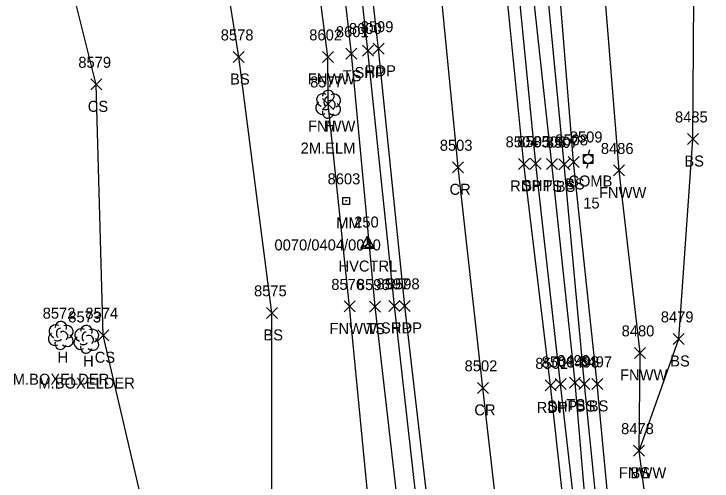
# Model space of a CAD drawing. Extents: x 1439173 to 1457902, y 641926 to 659889.
# Drawn here: x 1448293 to 1448419.9, y 645547.6 to 645632.4 of the extents above; entities that cross this region are included whole.
import ezdxf

# ---------------------------------------------------------------- set-up
doc = ezdxf.new("R2010")
doc.units = 0
for name, color, linetype in [('C_A', 7, 'Continuous'), ('C_I', 7, 'Continuous'), ('CPSM', 7, 'Continuous'), ('L_A', 7, 'Continuous'), ('L_C', 7, 'Continuous'), ('L_I', 7, 'Continuous'), ('L_TIC', 7, 'Continuous'), ('LELB', 7, 'Continuous'), ('LFNC', 7, 'Continuous'), ('LTD', 7, 'Continuous'), ('P_A', 7, 'Continuous'), ('P_I', 7, 'Continuous'), ('P_TIC', 7, 'Continuous'), ('PET', 7, 'Continuous'), ('PRC', 7, 'Continuous'), ('PSP', 7, 'Continuous'), ('S_A', 7, 'Continuous'), ('S_C', 7, 'Continuous'), ('S_I', 7, 'Continuous'), ('SRM', 7, 'Continuous'), ('U_A', 7, 'Continuous'), ('U_C', 7, 'Continuous'), ('U_I', 7, 'Continuous'), ('UP', 7, 'Continuous')]:
    doc.layers.add(name, color=color, linetype=linetype)

msp = doc.modelspace()

# ---------------------------------------------------------------- linework, layer by layer
at = {"layer": 'CPSM'}
for p, q in [((1448356.07, 645589.88), (1448357.32, 645592.05)), ((1448358.57, 645589.88), (1448357.32, 645592.05)), ((1448357.32, 645590.61), (1448357.32, 645592.05)), ((1448356.07, 645589.88), (1448357.32, 645590.61)), ((1448357.32, 645590.61), (1448357.32, 645590.61)), ((1448357.32, 645590.61), (1448358.57, 645589.88)), ((1448356.07, 645589.88), (1448358.57, 645589.88))]:
    msp.add_line(p, q, dxfattribs=at)
at = {"layer": 'L_TIC'}
for points in [[(1448353.36, 645624.18), (1448355.36, 645626.18)], [(1448355.36, 645624.18), (1448353.36, 645626.18)], [(1448332.87, 645623.59), (1448334.87, 645625.59)], [(1448334.87, 645623.59), (1448332.87, 645625.59)], [(1448349.08, 645623.6), (1448351.08, 645625.6)], [(1448351.08, 645623.6), (1448349.08, 645625.6)], [(1448306.99, 645618.62), (1448308.99, 645620.62)], [(1448308.99, 645618.62), (1448306.99, 645620.62)], [(1448349.12, 645615.05), (1448351.12, 645617.05)], [(1448351.12, 645615.05), (1448349.12, 645617.05)], [(1448415.45, 645608.69), (1448417.45, 645610.69)], [(1448417.45, 645608.69), (1448415.45, 645610.69)], [(1448389.82, 645604.16), (1448391.82, 645606.16)], [(1448391.82, 645604.16), (1448389.82, 645606.16)], [(1448392.06, 645604.09), (1448394.06, 645606.09)], [(1448394.06, 645604.09), (1448392.06, 645606.09)], [(1448393.76, 645604.53), (1448395.76, 645606.53)], [(1448395.76, 645604.53), (1448393.76, 645606.53)], [(1448402.03, 645602.97), (1448404.03, 645604.97)], [(1448404.03, 645602.97), (1448402.03, 645604.97)], [(1448353.03, 645578.28), (1448355.03, 645580.28)], [(1448355.03, 645578.28), (1448353.03, 645580.28)], [(1448357.67, 645578.24), (1448359.67, 645580.24)], [(1448359.67, 645578.24), (1448357.67, 645580.24)], [(1448338.92, 645577.11), (1448340.92, 645579.11)], [(1448340.92, 645577.11), (1448338.92, 645579.11)], [(1448308.26, 645573.04), (1448310.26, 645575.04)], [(1448310.26, 645573.04), (1448308.26, 645575.04)], [(1448412.88, 645572.37), (1448414.88, 645574.37)], [(1448414.88, 645572.37), (1448412.88, 645574.37)], [(1448405.84, 645569.83), (1448407.84, 645571.83)], [(1448407.84, 645569.83), (1448405.84, 645571.83)], [(1448394.04, 645564.43), (1448396.04, 645566.43)], [(1448396.04, 645564.43), (1448394.04, 645566.43)], [(1448395.72, 645564.18), (1448397.72, 645566.18)], [(1448397.72, 645564.18), (1448395.72, 645566.18)], [(1448398.06, 645564.21), (1448400.06, 645566.21)], [(1448400.06, 645564.21), (1448398.06, 645566.21)], [(1448405.65, 645552.07), (1448407.65, 645554.07)], [(1448407.65, 645552.07), (1448405.65, 645554.07)], [(1448405.65, 645552.07), (1448407.65, 645554.07)], [(1448407.65, 645552.07), (1448405.65, 645554.07)]]:
    msp.add_lwpolyline(points, dxfattribs=at)
at = {"layer": 'LELB'}
for points in [[(1448410.33, 645213.44), (1448402.27, 645258.19), (1448399.36, 645272.36), (1448392.8, 645314.92), (1448385.07, 645365.3), (1448380.5, 645404.06), (1448377.54, 645422.2), (1448372.05, 645464.88), (1448368.58, 645502.26), (1448364, 645532.71), (1448358.67, 645579.24), (1448354.36, 645625.18), (1448350.77, 645657.17), (1448347.93, 645686.18), (1448344.39, 645713.89), (1448343.18, 645734.53), (1448337.95, 645782.1), (1448332.15, 645838.85), (1448327.4, 645886.44), (1448322.84, 645936.93), (1448319.75, 645969.88), (1448314.6, 646019.57), (1448310.3, 646060.99), (1448309.1, 646066.32)], [(1448339.89, 645520.89), (1448339.92, 645578.11), (1448333.87, 645624.59), (1448328.8, 645656.21), (1448317.36, 645666.31), (1448329.07, 645677.57), (1448315.21, 645683.79), (1448294.81, 645688.61), (1448295.37, 645705.22), (1448321.93, 645710.44), (1448330.01, 645716.85), (1448328.68, 645729.34), (1448327.94, 645753.22), (1448321.76, 645792.82), (1448323.51, 645829.69), (1448322.34, 645839.12), (1448317.75, 645874.06), (1448316.24, 645881.04), (1448311.47, 645911.46), (1448307.56, 645942.57)], [(1448405.75, 645492.25), (1448401.29, 645509.86), (1448397.55, 645536.24), (1448395.04, 645565.43), (1448390.82, 645605.16), (1448386.96, 645640.23), (1448382.46, 645691.87), (1448378.2, 645742.37), (1448373.3, 645784.08), (1448367.48, 645837.06), (1448362.7, 645887.98), (1448357.78, 645935.33)], [(1448412.77, 645435.45), (1448410.01, 645448.83), (1448407.82, 645469.28), (1448405.75, 645492.25), (1448403.36, 645510.08), (1448399.67, 645536.29), (1448396.72, 645565.18), (1448393.06, 645605.09), (1448389.62, 645640.48), (1448384.68, 645691.72), (1448381.69, 645742.83), (1448376.05, 645783.94), (1448369.5, 645836.29), (1448364.45, 645888.25), (1448360.02, 645935.41)], [(1448403.36, 645510.08), (1448401.75, 645536.42), (1448399.06, 645565.21), (1448394.76, 645605.53), (1448391.92, 645640.7), (1448388.23, 645691.54), (1448383.69, 645733.41), (1448383.38, 645743.17), (1448378.66, 645784.47), (1448371.77, 645836.33), (1448366.28, 645888.78), (1448363.29, 645935.65)], [(1448406.65, 645553.07), (1448413.88, 645573.37), (1448416.45, 645609.69), (1448416.69, 645643.68), (1448431.28, 645649.5), (1448456.82, 645674.35), (1448466.81, 645700.96), (1448467.19, 645730.29), (1448471.42, 645758.01)], [(1448396.33, 645152.61), (1448370.6, 645148.13), (1448370.49, 645190.37), (1448357.56, 645241.66), (1448352.71, 645292.86), (1448342.42, 645338.3), (1448336.92, 645366.29), (1448333.84, 645401.38), (1448329.08, 645425.03), (1448327.96, 645468.61), (1448321.99, 645519.59), (1448309.26, 645574.04), (1448307.99, 645619.62), (1448298.28, 645658.41), (1448294.81, 645688.61)]]:
    msp.add_lwpolyline(points, dxfattribs=at)
at = {"layer": 'LFNC'}
for points in [[(1448372.23, 645420.35), (1448366.05, 645474.35), (1448359.55, 645522.49), (1448354.03, 645579.28), (1448350.12, 645616.05), (1448350.08, 645624.6), (1448345.93, 645656.55), (1448344.63, 645677.79), (1448343.93, 645685.63), (1448341.99, 645700.46), (1448340.11, 645712.99), (1448337.33, 645734.42), (1448335.79, 645757.3), (1448331.24, 645795.41), (1448326.75, 645834.64), (1448321.82, 645874.28), (1448318.79, 645912.6), (1448315.81, 645942.84), (1448313.25, 645968.88), (1448307.85, 646014.51)], [(1448408.71, 645537.14), (1448406.65, 645553.07), (1448406.84, 645570.83), (1448403.03, 645603.97), (1448399.71, 645645.27), (1448398.94, 645666), (1448395.14, 645693.25), (1448392.68, 645733.91), (1448422.44, 645749.73), (1448449.06, 645754.04), (1448471.42, 645758.01), (1448503.03, 645761.43), (1448501.38, 645735.65), (1448498.9, 645710.49)]]:
    msp.add_lwpolyline(points, dxfattribs=at)
at = {"layer": 'LTD'}
for p, q in [((1448350.12, 645616.05), (1448350.12, 645616.05)), ((1448350.12, 645616.05), (1448350.12, 645616.05)), ((1448301.5, 645574.05), (1448301.5, 645574.05)), ((1448301.5, 645574.05), (1448301.5, 645574.05)), ((1448306.16, 645573.36), (1448306.16, 645573.36)), ((1448306.16, 645573.36), (1448306.16, 645573.36))]:
    msp.add_line(p, q, dxfattribs=at)
for centre in [(1448350.17, 645617.49), (1448301.55, 645575.49), (1448306.2, 645574.79)]:
    msp.add_arc(centre, 1.05, 335.5272, 180.9563, dxfattribs=at)
for centre, major_axis, ratio, start_param, end_param in [((1448349.33, 645616.72), (1.21, -0.51), 0.895232, 1.570796, 4.712389), ((1448349.91, 645616.51), (-0.208, -0.792), 0.645439, 3.141593, 6.283185), ((1448351.16, 645616.64), (-1.14, -0.48), 0.949671, 1.570796, 4.712389), ((1448349.04, 645615.34), (0.58, -1.04), 0.959034, 3.141593, 6.283185), ((1448350.62, 645615.89), (-0.5, 0.667), 0.989748, 3.141593, 6.283185), ((1448351.12, 645615.22), (-1.09, 0.79), 0.841452, 1.570796, 4.712389), ((1448350.12, 645614.55), (0.26, 1.06), 0.942809, 1.570796, 4.712389), ((1448349.66, 645615.3), (-0.625, -0.083), 0.423636, 0, 3.141593), ((1448300.71, 645574.72), (1.21, -0.51), 0.895232, 1.570796, 4.712389), ((1448301.29, 645574.51), (-0.208, -0.792), 0.645439, 3.141593, 6.283185), ((1448302.54, 645574.64), (-1.14, -0.48), 0.949671, 1.570796, 4.712389), ((1448305.36, 645574.03), (1.21, -0.51), 0.895232, 1.570796, 4.712389), ((1448300.42, 645573.34), (0.58, -1.04), 0.959034, 3.141593, 6.283185), ((1448302, 645573.89), (-0.5, 0.667), 0.989748, 3.141593, 6.283185), ((1448302.5, 645573.22), (-1.09, 0.79), 0.841452, 1.570796, 4.712389), ((1448305.95, 645573.82), (-0.208, -0.792), 0.645439, 3.141593, 6.283185), ((1448306.66, 645573.19), (-0.5, 0.667), 0.989748, 3.141593, 6.283185), ((1448307.2, 645573.94), (-1.14, -0.48), 0.949671, 1.570796, 4.712389), ((1448301.5, 645572.55), (0.26, 1.06), 0.942809, 1.570796, 4.712389), ((1448301.04, 645573.3), (-0.625, -0.083), 0.423636, 0, 3.141593), ((1448305.07, 645572.65), (0.58, -1.04), 0.959034, 3.141593, 6.283185), ((1448307.16, 645572.53), (-1.09, 0.79), 0.841452, 1.570796, 4.712389), ((1448306.16, 645571.86), (0.26, 1.06), 0.942809, 1.570796, 4.712389), ((1448305.7, 645572.61), (-0.625, -0.083), 0.423636, 0, 3.141593)]:
    msp.add_ellipse(centre, major_axis=major_axis, ratio=ratio, start_param=start_param, end_param=end_param, dxfattribs=at)
at = {"layer": 'P_TIC'}
for points in [[(1448356.38, 645624.76), (1448358.38, 645626.76)], [(1448358.38, 645624.76), (1448356.38, 645626.76)], [(1448358.32, 645625.09), (1448360.32, 645627.09)], [(1448360.32, 645625.09), (1448358.32, 645627.09)], [(1448384.73, 645604.17), (1448386.73, 645606.17)], [(1448386.73, 645604.17), (1448384.73, 645606.17)], [(1448386.87, 645604.22), (1448388.87, 645606.22)], [(1448388.87, 645604.22), (1448386.87, 645606.22)], [(1448372.77, 645603.55), (1448374.77, 645605.55)], [(1448374.77, 645603.55), (1448372.77, 645605.55)], [(1448361.18, 645578.37), (1448363.18, 645580.37)], [(1448363.18, 645578.37), (1448361.18, 645580.37)], [(1448363.07, 645578.37), (1448365.07, 645580.37)], [(1448365.07, 645578.37), (1448363.07, 645580.37)], [(1448377.28, 645563.48), (1448379.28, 645565.48)], [(1448379.28, 645563.48), (1448377.28, 645565.48)], [(1448389.56, 645563.93), (1448391.56, 645565.93)], [(1448391.56, 645563.93), (1448389.56, 645565.93)], [(1448391.38, 645564.18), (1448393.38, 645566.18)], [(1448393.38, 645564.18), (1448391.38, 645566.18)]]:
    msp.add_lwpolyline(points, dxfattribs=at)
at = {"layer": 'PET'}
for points in [[(1448415.59, 645214.45), (1448407.8, 645259.58), (1448405.4, 645273.6), (1448398.38, 645316.04), (1448390.67, 645367.01), (1448385.5, 645404.88), (1448383.09, 645423.2), (1448377.71, 645465.59), (1448373.01, 645502.47), (1448369.4, 645533.38), (1448364.07, 645579.37), (1448359.32, 645626.09), (1448355.66, 645658.09), (1448352.76, 645687), (1448347.61, 645738.62), (1448343.09, 645781.34), (1448336.3, 645838.65), (1448331.09, 645886.39), (1448326.63, 645936.53)], [(1448443.5, 645192.53), (1448434.94, 645239.98), (1448429.99, 645267.41), (1448423.88, 645303.9), (1448416.59, 645352.86), (1448409.48, 645406.38), (1448407.14, 645423.82), (1448401.2, 645468.9), (1448395.52, 645519.79), (1448390.56, 645564.93), (1448385.73, 645605.17), (1448382.23, 645639.77), (1448376.98, 645691.5), (1448372.16, 645742.34), (1448368.41, 645784.44), (1448364.57, 645838.37), (1448359.79, 645887.7), (1448355.35, 645935.31)]]:
    msp.add_lwpolyline(points, dxfattribs=at)
at = {"layer": 'PRC'}
msp.add_lwpolyline([(1448432.04, 645191.01), (1448423.23, 645238.86), (1448418.18, 645266.5), (1448412.46, 645302.65), (1448405.18, 645350.69), (1448397.65, 645404.37), (1448395.39, 645422.98), (1448389.6, 645467.56), (1448383.62, 645518.18), (1448378.28, 645564.48), (1448373.77, 645604.55), (1448370.44, 645638.71), (1448365.01, 645690.62), (1448359.88, 645740), (1448355.44, 645783.01), (1448350.36, 645838.06), (1448345.39, 645887.63), (1448340.89, 645937.21)], dxfattribs=at)
at = {"layer": 'PSP'}
for points in [[(1448412.77, 645213.75), (1448405.32, 645259.04), (1448402.68, 645272.84), (1448395.81, 645315.4), (1448388.51, 645366.24), (1448383.46, 645404.43), (1448380.91, 645423.17), (1448375.81, 645465.13), (1448371.16, 645502.31), (1448367.42, 645533.19), (1448362.18, 645579.37), (1448357.38, 645625.76), (1448353.78, 645658.1), (1448351.21, 645686.68), (1448345.83, 645738.56), (1448341.56, 645781.11), (1448336.3, 645838.65)], [(1448445.7, 645193.09), (1448437.06, 645240), (1448432.32, 645267.62), (1448425.9, 645304.13), (1448419.15, 645353.02), (1448411.55, 645406.57), (1448409.06, 645424.19), (1448403.66, 645468.94), (1448397.6, 645519.68), (1448392.38, 645565.18), (1448387.87, 645605.22), (1448384.49, 645639.79), (1448379.25, 645691.61), (1448373.95, 645742.41), (1448369.71, 645784.24), (1448364.57, 645838.37)]]:
    msp.add_lwpolyline(points, dxfattribs=at)
at = {"layer": 'SRM'}
msp.add_lwpolyline([(1448352.79, 645599.07), (1448354.04, 645599.07), (1448354.04, 645597.82), (1448352.79, 645597.82)], close=True, dxfattribs=at)
msp.add_circle((1448353.41, 645598.45), 0.0833, dxfattribs=at)
at = {"layer": 'UP'}
for p, q in [((1448397.65, 645607.72), (1448397.4, 645606.89)), ((1448396.57, 645605.22), (1448396.57, 645606.89)), ((1448396.57, 645606.89), (1448398.24, 645606.89)), ((1448397.4, 645606.06), (1448397.4, 645606.06)), ((1448398.24, 645606.89), (1448398.24, 645605.22)), ((1448398.24, 645605.22), (1448396.57, 645605.22)), ((1448397.15, 645604.39), (1448397.4, 645605.22))]:
    msp.add_line(p, q, dxfattribs=at)
msp.add_circle((1448397.4, 645606.06), 0.833, dxfattribs=at)

# ---------------------------------------------------------------- texts
at = {"layer": 'C_A'}
msp.add_text('HVCTRL', height=2, dxfattribs=at).set_placement((1448352.01, 645585.61))
at = {"layer": 'C_I'}
msp.add_text('250', height=2, dxfattribs=at).set_placement((1448354.87, 645593.61))
at = {"layer": 'L_A'}
for s, p in [('BS', (1448332.31, 645619.59)), ('FNWW', (1448346.43, 645619.6)), ('TS', (1448352.77, 645620.18)), ('CS', (1448306.43, 645614.62)), ('FNWW', (1448346.47, 645611.05)), ('H', (1448349.56, 645611.05)), ('BS', (1448414.89, 645604.69)), ('TS', (1448389.23, 645600.16)), ('BS', (1448391.5, 645600.09)), ('BS', (1448393.2, 645600.53)), ('FNWW', (1448399.37, 645598.97)), ('FNWW', (1448350.38, 645574.28)), ('TS', (1448357.08, 645574.24)), ('BS', (1448338.36, 645573.11)), ('H', (1448300.93, 645569.05)), ('H', (1448305.59, 645568.36)), ('CS', (1448307.7, 645569.04)), ('BS', (1448412.32, 645568.37)), ('FNWW', (1448403.19, 645565.83)), ('TS', (1448393.45, 645560.43)), ('BS', (1448395.16, 645560.18)), ('BS', (1448397.5, 645560.21)), ('FNWW', (1448402.99, 645548.07)), ('BS', (1448405.09, 645548.07))]:
    msp.add_text(s, height=2, dxfattribs=at).set_placement(p)
at = {"layer": 'L_C'}
for s, p in [('2M.ELM', (1448345.13, 645607.05)), ('M.BOXELDER', (1448292.8, 645565.05)), ('M.BOXELDER', (1448297.46, 645564.36))]:
    msp.add_text(s, height=2, dxfattribs=at).set_placement(p)
at = {"layer": 'L_I'}
for s, p in [('8601', (1448351.54, 645628.18)), ('8578', (1448330.61, 645627.59)), ('8602', (1448346.7, 645627.6)), ('8579', (1448304.72, 645622.62)), ('8577', (1448346.86, 645619.05)), ('8577', (1448346.86, 645619.05)), ('8485', (1448413.19, 645612.69)), ('8506', (1448387.43, 645608.16)), ('8507', (1448389.72, 645608.09)), ('8508', (1448391.42, 645608.53)), ('8486', (1448399.71, 645606.97)), ('8576', (1448350.71, 645582.28)), ('8596', (1448355.36, 645582.24)), ('8575', (1448336.66, 645581.11)), ('8572', (1448298.24, 645577.05)), ('8573', (1448302.9, 645576.36)), ('8574', (1448306, 645577.04)), ('8479', (1448410.61, 645576.37)), ('8480', (1448403.49, 645573.83)), ('8499', (1448391.77, 645568.43)), ('8498', (1448393.46, 645568.18)), ('8497', (1448395.8, 645568.21)), ('8478', (1448403.39, 645556.07)), ('8478', (1448403.39, 645556.07))]:
    msp.add_text(s, height=2, dxfattribs=at).set_placement(p)
at = {"layer": 'P_A'}
for s, p in [('SHP', (1448354.92, 645620.76)), ('RDP', (1448356.81, 645621.09)), ('RDP', (1448383.22, 645600.17)), ('SHP', (1448385.41, 645600.22)), ('CR', (1448372.2, 645599.55)), ('SHP', (1448359.72, 645574.37)), ('RDP', (1448361.56, 645574.37)), ('CR', (1448376.71, 645559.48)), ('RDP', (1448388.05, 645559.93)), ('SHP', (1448389.92, 645560.18))]:
    msp.add_text(s, height=2, dxfattribs=at).set_placement(p)
at = {"layer": 'P_I'}
for s, p in [('8600', (1448353.91, 645628.76)), ('8599', (1448356.05, 645629.09)), ('8504', (1448382.39, 645608.17)), ('8505', (1448384.53, 645608.22)), ('8503', (1448370.43, 645607.55)), ('8597', (1448358.92, 645582.37)), ('8598', (1448360.81, 645582.37)), ('8502', (1448374.94, 645567.48)), ('8501', (1448387.79, 645567.93)), ('8500', (1448388.96, 645568.18))]:
    msp.add_text(s, height=2, dxfattribs=at).set_placement(p)
at = {"layer": 'S_A'}
msp.add_text('MM', height=2, dxfattribs=at).set_placement((1448351.6, 645593.45))
at = {"layer": 'S_C'}
msp.add_text('0070/0404/0040', height=2, dxfattribs=at).set_placement((1448340.38, 645589.45))
at = {"layer": 'S_I'}
msp.add_text('8603', height=2, dxfattribs=at).set_placement((1448350.03, 645601.45))
at = {"layer": 'U_A'}
msp.add_text('COMB', height=2, dxfattribs=at).set_placement((1448393.79, 645601.06))
at = {"layer": 'U_C'}
msp.add_text('15', height=2, dxfattribs=at).set_placement((1448396.51, 645597.06))
at = {"layer": 'U_I'}
msp.add_text('8509', height=2, dxfattribs=at).set_placement((1448394.06, 645609.06))

doc.saveas('drawing.dxf')
